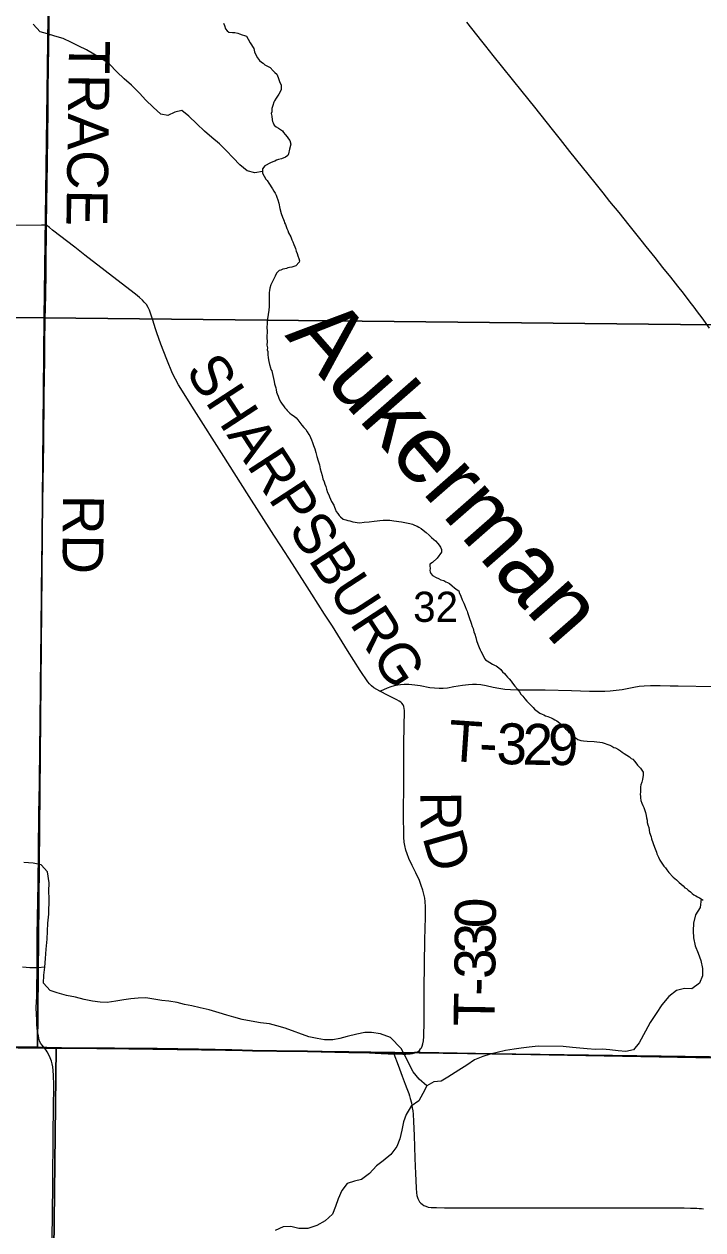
# Model space of a CAD drawing. Extents: x 0 to 34, y 0 to 22.
# Drawn here: x 4.443 to 5.385, y 18.105 to 19.778 of the extents above; entities that cross this region are included whole.
import ezdxf

# ---------------------------------------------------------------- set-up
doc = ezdxf.new("R2010")
doc.units = 0
for name, color, linetype in [('GM_X_Corporation', 7, 'Continuous'), ('GM_X_County_Road', 7, 'Continuous'), ('GM_X_County_Road_Text', 7, 'Continuous'), ('GM_X_Minor_River', 7, 'Continuous'), ('GM_X_Minor_River_Text', 7, 'Continuous'), ('GM_X_Section_Text', 7, 'Continuous'), ('GM_X_State_Route', 7, 'Continuous'), ('GM_X_Township_Road', 7, 'Continuous'), ('GM_X_Township_Road_Text', 7, 'Continuous')]:
    doc.layers.add(name, color=color, linetype=linetype)

msp = doc.modelspace()

# ---------------------------------------------------------------- linework, layer by layer
at = {"layer": 'GM_X_Corporation'}
for points in [[(3.5146, 20.3904), (4.4842, 20.3804), (4.4706, 19.3704), (3.4987, 19.3808), (3.5147, 20.359)], [(4.4842, 20.3804), (5.4958, 20.3705), (5.4859, 19.36), (4.4706, 19.3704)], [(4.4706, 19.3704), (4.4615, 18.3587), (3.4912, 18.3726), (3.4987, 19.3808)], [(5.4859, 19.36), (5.4612, 18.3442), (4.4872, 18.3578), (4.4615, 18.3587), (4.4706, 19.3704)], [(3.4912, 18.3726), (4.4615, 18.3587), (4.4872, 18.3578), (4.475, 17.2762), (3.4847, 17.2912)], [(4.4872, 18.3578), (5.4612, 18.3442), (5.4991, 18.3437), (5.4781, 17.2612), (4.475, 17.2762)]]:
    msp.add_lwpolyline(points, close=True, dxfattribs=at)
for points in [[(6.2163, 18.3289), (4.9929, 18.3512), (4.9848, 18.3513), (4.9816, 18.3505), (4.9785, 18.35), (4.9754, 18.3497), (4.9725, 18.3496), (4.9681, 18.3496), (4.9558, 18.3497), (4.9478, 18.35), (4.9459, 18.3501), (4.9381, 18.3505), (4.9297, 18.3508), (4.9142, 18.3515), (4.8934, 18.3519), (4.8738, 18.3523), (4.8361, 18.353), (4.7933, 18.3536), (4.7598, 18.3542), (4.7312, 18.3548), (4.6851, 18.3558), (4.6275, 18.3567), (4.605, 18.3569), (4.5681, 18.3572), (4.5437, 18.3574), (4.4946, 18.3578), (4.4812, 18.3578), (4.471, 18.3577), (4.4651, 18.3578), (4.3971, 18.3585)], [(4.3971, 18.3585), (4.4651, 18.3578), (4.471, 18.3577), (4.4812, 18.3578), (4.4946, 18.3578), (4.5437, 18.3574), (4.5681, 18.3572), (4.605, 18.3569), (4.6275, 18.3567), (4.6851, 18.3558), (4.7312, 18.3548), (4.7598, 18.3542), (4.7933, 18.3536), (4.8361, 18.353), (4.8738, 18.3523), (4.8934, 18.3519), (4.9142, 18.3515), (4.9297, 18.3508), (4.9381, 18.3505), (4.9459, 18.3501), (4.9478, 18.35), (4.9558, 18.3497), (4.9681, 18.3496), (4.9725, 18.3496), (4.9754, 18.3497), (4.9785, 18.35), (4.9816, 18.3505), (4.9848, 18.3513), (4.9929, 18.3512), (6.2163, 18.3289)]]:
    msp.add_lwpolyline(points, dxfattribs=at)
at = {"layer": 'GM_X_County_Road'}
for points in [[(4.4712, 18.3572), (4.4678, 18.3613), (4.4657, 18.3643), (4.4643, 18.3675), (4.4634, 18.3712), (4.4627, 18.3744), (4.4616, 18.3808), (4.4611, 18.3845), (4.4606, 18.39), (4.4603, 18.3963), (4.46, 18.404), (4.4598, 18.4138), (4.4603, 18.429), (4.4609, 18.4765), (4.4611, 18.514), (4.4622, 18.5858), (4.4629, 18.6294), (4.4635, 18.6835), (4.4641, 18.7233), (4.4647, 18.7767), (4.465, 18.8046), (4.4657, 18.863), (4.4661, 18.8951), (4.4676, 19.0332), (4.4701, 19.1963), (4.4709, 19.2625), (4.4714, 19.3122), (4.4717, 19.3352), (4.4723, 19.3687), (4.4728, 19.4016), (4.4733, 19.4344), (4.4735, 19.4569), (4.4738, 19.4842), (4.474, 19.4994), (4.4744, 19.5295), (4.4753, 19.5861), (4.4758, 19.6233), (4.4761, 19.6582), (4.4764, 19.6872), (4.4772, 19.7476), (4.4779, 19.8035)], [(4.4727, 17.2893), (4.4727, 17.2905), (4.4727, 17.3067), (4.474, 17.3955), (4.4755, 17.5136), (4.4765, 17.5944), (4.4782, 17.7292), (4.4793, 17.8391), (4.4802, 17.9473), (4.4812, 18.0329), (4.482, 18.0907), (4.4827, 18.1677), (4.4833, 18.2397), (4.4839, 18.3062), (4.4838, 18.3193), (4.4834, 18.3262), (4.4827, 18.3312), (4.4817, 18.3355), (4.4807, 18.3391), (4.4789, 18.3438), (4.4765, 18.3487), (4.4749, 18.3519), (4.4733, 18.3544), (4.4712, 18.3572)]]:
    msp.add_lwpolyline(points, dxfattribs=at)
at = {"layer": 'GM_X_Minor_River'}
for points in [[(4.7736, 19.5738), (4.7632, 19.5717), (4.7526, 19.5745), (4.7421, 19.5827), (4.7332, 19.5927), (4.7235, 19.6028), (4.7138, 19.612), (4.7033, 19.6206), (4.6933, 19.6295), (4.6828, 19.6399), (4.6716, 19.6504), (4.6619, 19.6582), (4.652, 19.6557), (4.6424, 19.6513), (4.6326, 19.653), (4.6222, 19.6627), (4.6117, 19.6724), (4.6028, 19.6824), (4.592, 19.6932), (4.5819, 19.7021), (4.5715, 19.7118), (4.5614, 19.7223), (4.5506, 19.7297), (4.5397, 19.7363), (4.5295, 19.7426), (4.519, 19.7477), (4.5085, 19.7525), (4.4972, 19.758), (4.4855, 19.7616), (4.4753, 19.7645), (4.4651, 19.7673), (4.4554, 19.7781)], [(4.7197, 19.7792), (4.7208, 19.7761), (4.7225, 19.7714), (4.7247, 19.7687), (4.7269, 19.7671), (4.7322, 19.7665), (4.7352, 19.7664), (4.7394, 19.7655), (4.742, 19.7646), (4.7457, 19.7634), (4.7487, 19.7625), (4.7513, 19.7613), (4.7538, 19.757), (4.7567, 19.7519), (4.7617, 19.7441), (4.7627, 19.7395), (4.7645, 19.7356), (4.7666, 19.7314), (4.7695, 19.7278), (4.7724, 19.7251), (4.7747, 19.7238), (4.7769, 19.7218), (4.7843, 19.7178), (4.7883, 19.7134), (4.7909, 19.7111), (4.7938, 19.7087), (4.7956, 19.704), (4.7973, 19.6986), (4.7994, 19.6932), (4.7996, 19.6894), (4.7995, 19.6867), (4.7963, 19.6808), (4.7927, 19.6752), (4.7903, 19.6718), (4.7894, 19.6696), (4.7881, 19.6654), (4.7868, 19.6609), (4.7867, 19.6563), (4.7859, 19.6541), (4.7865, 19.6506), (4.7871, 19.6453), (4.7874, 19.643), (4.7884, 19.641), (4.7898, 19.6379), (4.7928, 19.6356), (4.7957, 19.6335), (4.7987, 19.6319), (4.8013, 19.6299), (4.8027, 19.6276), (4.8053, 19.6248), (4.8078, 19.6217), (4.8096, 19.6189), (4.8118, 19.6166), (4.8128, 19.6116), (4.811, 19.6044), (4.8097, 19.598), (4.8088, 19.5957), (4.8057, 19.5936), (4.8003, 19.5911), (4.7957, 19.5901), (4.793, 19.5891), (4.7907, 19.588), (4.788, 19.587), (4.785, 19.5856), (4.7768, 19.5813), (4.7737, 19.5772), (4.7736, 19.5738), (4.7738, 19.5715), (4.7785, 19.5629), (4.7803, 19.561), (4.7825, 19.5575), (4.7875, 19.5497), (4.7893, 19.5465), (4.7911, 19.5434), (4.7925, 19.5407), (4.7935, 19.538), (4.7949, 19.5345), (4.7963, 19.5295), (4.7979, 19.5222), (4.7995, 19.5153), (4.8013, 19.5103), (4.8027, 19.5068), (4.8037, 19.5045), (4.8044, 19.5022), (4.8054, 19.4999), (4.8075, 19.4945), (4.8089, 19.4917), (4.81, 19.4883), (4.8128, 19.4828), (4.8142, 19.479), (4.8156, 19.4759), (4.817, 19.4724), (4.8184, 19.4693)], [(4.8184, 19.4693), (4.8194, 19.4666), (4.8204, 19.4631), (4.8218, 19.4597), (4.8229, 19.4566), (4.8243, 19.4531), (4.8249, 19.4496), (4.8248, 19.4477), (4.8201, 19.4426), (4.8144, 19.4409), (4.8113, 19.4406), (4.809, 19.4399), (4.8071, 19.4392), (4.8048, 19.4386), (4.8017, 19.4379), (4.7991, 19.4369), (4.7968, 19.4362), (4.7932, 19.4325), (4.7912, 19.4284), (4.7855, 19.4164), (4.7838, 19.4119), (4.7833, 19.4085), (4.7828, 19.4055), (4.783, 19.4013), (4.7829, 19.3978), (4.7831, 19.3936), (4.7829, 19.3864), (4.7823, 19.3811), (4.7817, 19.375), (4.7808, 19.369), (4.7802, 19.3644), (4.7801, 19.3614), (4.7796, 19.3587), (4.7799, 19.3557), (4.7802, 19.3534), (4.7801, 19.3496), (4.7799, 19.3461), (4.7798, 19.3427), (4.78, 19.3378), (4.7799, 19.3328), (4.7805, 19.329), (4.7804, 19.3263), (4.7811, 19.324), (4.7813, 19.3198), (4.7815, 19.3152), (4.7825, 19.3102), (4.7835, 19.3056), (4.7848, 19.3014), (4.7855, 19.2991), (4.7866, 19.2968), (4.7872, 19.2945), (4.7898, 19.2822), (4.7905, 19.2791), (4.7915, 19.2764), (4.7922, 19.2733), (4.7925, 19.2707), (4.7931, 19.2676), (4.7942, 19.2653), (4.7956, 19.2618), (4.7969, 19.2575), (4.7991, 19.2537), (4.8009, 19.2509), (4.8027, 19.2486), (4.8048, 19.2458), (4.8067, 19.2439), (4.8081, 19.2419), (4.8096, 19.24), (4.8118, 19.2383), (4.814, 19.2364), (4.8177, 19.2339), (4.8203, 19.2319), (4.8228, 19.2288), (4.8254, 19.2253), (4.8283, 19.2218), (4.8312, 19.2186), (4.8337, 19.2155), (4.8359, 19.2123), (4.838, 19.2088), (4.8395, 19.2069), (4.8405, 19.2046), (4.8419, 19.2011), (4.8433, 19.1976), (4.8447, 19.1934), (4.8464, 19.1887), (4.8478, 19.1837), (4.8491, 19.178), (4.8508, 19.1722), (4.8528, 19.1664), (4.8538, 19.161), (4.8565, 19.1518), (4.8575, 19.1472), (4.8592, 19.1429), (4.8603, 19.1399), (4.8616, 19.1364), (4.8627, 19.1329), (4.864, 19.1283), (4.8658, 19.1248), (4.8668, 19.1221), (4.8696, 19.1159), (4.8725, 19.1105), (4.8735, 19.1078)], [(4.8735, 19.1078), (4.8746, 19.1055), (4.876, 19.102), (4.8781, 19.0989), (4.88, 19.0965), (4.8818, 19.0945), (4.8858, 19.0913), (4.8892, 19.0901), (4.8922, 19.0892), (4.8948, 19.0887), (4.8993, 19.0874), (4.9024, 19.0869), (4.905, 19.0868), (4.9088, 19.0863), (4.9149, 19.0869), (4.9217, 19.0874), (4.9286, 19.0886), (4.9328, 19.0889), (4.9366, 19.0895), (4.9411, 19.0897), (4.9461, 19.0899), (4.9502, 19.0898), (4.9562, 19.0888), (4.9596, 19.0883), (4.9627, 19.0878), (4.9664, 19.0873), (4.9781, 19.085), (4.9819, 19.0841), (4.9848, 19.0828), (4.9882, 19.0815), (4.9908, 19.0803), (4.9938, 19.0783), (4.9967, 19.0759), (5.0008, 19.0727), (5.0048, 19.0691), (5.0081, 19.0656), (5.0114, 19.0628), (5.014, 19.0612), (5.0169, 19.0573), (5.0187, 19.0553), (5.0209, 19.0522), (5.0223, 19.0491), (5.0222, 19.0453), (5.0162, 19.0371), (5.0096, 19.0309), (5.0061, 19.0287), (5.006, 19.0264), (5.0062, 19.0226), (5.0061, 19.02), (5.0064, 19.018), (5.0075, 19.0157), (5.0097, 19.013), (5.0149, 19.0101), (5.0179, 19.0089), (5.0212, 19.0072), (5.0254, 19.0059), (5.0283, 19.0043), (5.0306, 19.0035), (5.0332, 19.0018), (5.0368, 18.9987), (5.0402, 18.9959), (5.0439, 18.9931), (5.0461, 18.9919), (5.0468, 18.9896), (5.0489, 18.9845), (5.0509, 18.9791), (5.0531, 18.9745), (5.0548, 18.9702), (5.0562, 18.9664), (5.0576, 18.9636), (5.0583, 18.9617), (5.0597, 18.9575), (5.0607, 18.9548), (5.0631, 18.9467), (5.0648, 18.9424), (5.0662, 18.9393), (5.0665, 18.9374), (5.0672, 18.9351), (5.0682, 18.9317), (5.0696, 18.927), (5.0709, 18.9228), (5.0727, 18.9178), (5.0744, 18.9132), (5.0758, 18.9101), (5.0769, 18.9081), (5.0786, 18.9046), (5.0818, 18.898), (5.0833, 18.8961), (5.0855, 18.8945), (5.0892, 18.8924), (5.0929, 18.89), (5.0959, 18.8888), (5.0981, 18.8875), (5.1018, 18.8847), (5.1044, 18.8824), (5.107, 18.8796), (5.1095, 18.8772), (5.1113, 18.8749), (5.1135, 18.8721), (5.1161, 18.8698), (5.1186, 18.8666)], [(5.1186, 18.8666), (5.1208, 18.8635), (5.1237, 18.8596), (5.1277, 18.8553), (5.1302, 18.8517), (5.1324, 18.8486), (5.1349, 18.8455), (5.1378, 18.8419), (5.1404, 18.8388), (5.143, 18.8364), (5.1448, 18.8345), (5.1477, 18.8317), (5.1492, 18.8297), (5.151, 18.8278), (5.1532, 18.8261), (5.1584, 18.8222), (5.1617, 18.8205), (5.164, 18.8197), (5.1666, 18.8184), (5.1696, 18.8172), (5.1718, 18.8163), (5.1741, 18.8155), (5.1771, 18.8142), (5.1796, 18.8126), (5.1823, 18.8114), (5.1863, 18.8082), (5.1944, 18.8003), (5.1966, 18.7983), (5.1984, 18.7963), (5.2017, 18.7932), (5.2061, 18.7892), (5.2091, 18.7872), (5.2113, 18.7856), (5.2154, 18.7843), (5.2192, 18.7838), (5.2241, 18.7832), (5.2339, 18.7829), (5.2377, 18.7823), (5.2419, 18.7818), (5.2449, 18.7813), (5.2494, 18.78), (5.2516, 18.7792), (5.2557, 18.7775), (5.2587, 18.7763), (5.2613, 18.7746), (5.2636, 18.7738), (5.2676, 18.7714), (5.2706, 18.7697), (5.2728, 18.7681), (5.2758, 18.7661), (5.2791, 18.7637), (5.2828, 18.7613), (5.2854, 18.7593), (5.2876, 18.7581), (5.2902, 18.7553), (5.2916, 18.753), (5.2942, 18.7498), (5.2982, 18.7455), (5.3018, 18.74), (5.302, 18.7358), (5.3011, 18.7302), (5.3002, 18.7264), (5.2989, 18.7226), (5.2984, 18.7196), (5.2982, 18.7128), (5.2977, 18.709), (5.2984, 18.707), (5.2983, 18.7044), (5.2989, 18.7009), (5.3003, 18.6971), (5.3017, 18.694), (5.3027, 18.6913), (5.3038, 18.6882), (5.3051, 18.6843), (5.3061, 18.6801), (5.3068, 18.6767), (5.3074, 18.6736), (5.3077, 18.6705), (5.3087, 18.6671), (5.3097, 18.6632), (5.311, 18.6563), (5.3131, 18.6505), (5.3137, 18.6475), (5.3178, 18.6359), (5.3185, 18.6336), (5.3196, 18.6313), (5.3203, 18.6293), (5.3209, 18.627), (5.322, 18.6251), (5.3231, 18.6224), (5.3252, 18.6181), (5.3277, 18.6138), (5.3306, 18.6099), (5.3331, 18.6072), (5.3349, 18.6048), (5.3378, 18.6009), (5.3437, 18.5946), (5.3459, 18.5926), (5.3481, 18.591), (5.3499, 18.589), (5.3521, 18.5871)], [(5.0016, 18.3048), (4.9912, 18.3141), (4.983, 18.3245), (4.9779, 18.3341), (4.9724, 18.3448), (4.9662, 18.3567), (4.9513, 18.3721), (4.9373, 18.3773), (4.9252, 18.3791), (4.9157, 18.3789), (4.9047, 18.3768), (4.8913, 18.3733), (4.881, 18.3708), (4.8711, 18.3687), (4.8598, 18.3689), (4.8495, 18.3706), (4.8378, 18.3731), (4.805, 18.3851), (4.7937, 18.3883), (4.7835, 18.3908), (4.771, 18.3925), (4.7578, 18.3947), (4.7457, 18.3972), (4.734, 18.4004), (4.7242, 18.4029), (4.7136, 18.4061), (4.6996, 18.4102), (4.6872, 18.4131), (4.6755, 18.4159), (4.6656, 18.418), (4.6554, 18.4205), (4.6437, 18.4222), (4.6339, 18.4235), (4.6119, 18.427), (4.6013, 18.4268), (4.591, 18.4258), (4.5811, 18.4245), (4.5701, 18.4224), (4.5583, 18.4208), (4.5484, 18.4209), (4.5378, 18.4223), (4.5261, 18.4248), (4.514, 18.428), (4.5016, 18.4305), (4.4887, 18.4338), (4.4789, 18.437), (4.4696, 18.4474), (4.4702, 18.4584), (4.4715, 18.4694), (4.4725, 18.4815), (4.4735, 18.4948), (4.4749, 18.5084), (4.4755, 18.5197), (4.4757, 18.5307), (4.4771, 18.5432), (4.4775, 18.5648), (4.4773, 18.5751), (4.4775, 18.5868), (4.4755, 18.6017), (4.4666, 18.6117), (4.4556, 18.6138), (4.4423, 18.6148)], [(5.3521, 18.5871), (5.3547, 18.5847), (5.3577, 18.5823), (5.3598, 18.5799), (5.3621, 18.5787), (5.3646, 18.5763), (5.3676, 18.5739), (5.3698, 18.572), (5.3724, 18.57), (5.375, 18.5687), (5.3776, 18.5671), (5.3802, 18.5659), (5.3824, 18.5646), (5.3854, 18.5626)], [(5.3824, 18.5646), (5.3811, 18.5522), (5.3744, 18.5421), (5.3719, 18.5308), (5.3714, 18.5202), (5.372, 18.5103), (5.374, 18.4993), (5.3784, 18.489), (5.382, 18.479), (5.3844, 18.4676), (5.3843, 18.4578), (5.3803, 18.4476), (5.3695, 18.4394), (5.3593, 18.44), (5.3482, 18.4372), (5.3374, 18.4287), (5.3277, 18.4175), (5.3199, 18.4055), (5.3117, 18.3927), (5.3054, 18.3807), (5.2964, 18.3646), (5.2887, 18.3549), (5.278, 18.3524), (5.2674, 18.3537), (5.2556, 18.3547), (5.2454, 18.3557), (5.2359, 18.3555), (5.2242, 18.3564), (5.2143, 18.3574), (5.2041, 18.3583), (5.1912, 18.3593), (5.1563, 18.36), (5.1438, 18.3587), (5.1327, 18.3574), (5.1232, 18.3557), (5.1111, 18.354), (5.0996, 18.3512), (5.0897, 18.3487), (5.0794, 18.3455), (5.0679, 18.3408), (5.0572, 18.3338), (5.0461, 18.3268), (5.0311, 18.3172), (5.0215, 18.3113), (5.0116, 18.3103), (5.0016, 18.3048), (4.9961, 18.2943), (4.9906, 18.2842), (4.9802, 18.2768), (4.9732, 18.2652), (4.9696, 18.255), (4.9671, 18.2433), (4.9642, 18.2316), (4.9602, 18.221), (4.9517, 18.2098), (4.9413, 18.2009), (4.9317, 18.1939), (4.922, 18.1831), (4.9112, 18.1749), (4.9013, 18.1728), (4.891, 18.1692), (4.8836, 18.1595), (4.8788, 18.1482), (4.8752, 18.1373), (4.8709, 18.1268), (4.8608, 18.1178), (4.8489, 18.1112), (4.8367, 18.1069), (4.8242, 18.1071), (4.8129, 18.1096), (4.8026, 18.1094), (4.7915, 18.1043)], [(4.4715, 18.4694), (4.4617, 18.4688), (4.451, 18.4686), (4.4408, 18.4696)]]:
    msp.add_lwpolyline(points, dxfattribs=at)
at = {"layer": 'GM_X_State_Route'}
msp.add_lwpolyline([(5.0567, 19.7806), (5.0776, 19.7544), (5.083, 19.7476), (5.0935, 19.7345), (5.1335, 19.6845), (5.151, 19.6627), (5.1759, 19.6317), (5.1868, 19.6179), (5.1999, 19.6015), (5.2347, 19.5578), (5.246, 19.5438), (5.2554, 19.5322), (5.268, 19.5168), (5.2819, 19.4993), (5.2912, 19.4876), (5.2986, 19.4783), (5.3055, 19.4696), (5.318, 19.4541), (5.3289, 19.4406), (5.3398, 19.427), (5.3498, 19.4143), (5.3575, 19.4046), (5.3669, 19.3923), (5.3722, 19.3855), (5.377, 19.3789), (5.3833, 19.3704), (5.3936, 19.3561)], dxfattribs=at)
at = {"layer": 'GM_X_Township_Road'}
for points in [[(4.4299, 19.4993), (4.467, 19.4994), (4.4698, 19.4994), (4.474, 19.4994)], [(4.9365, 18.8526), (4.9323, 18.8548), (4.9283, 18.8574), (4.9249, 18.8601), (4.9222, 18.8628), (4.92, 18.8656), (4.9094, 18.8812), (4.8918, 18.909), (4.8707, 18.9427), (4.8599, 18.9594), (4.8422, 18.9871), (4.8154, 19.029), (4.7993, 19.0541), (4.7895, 19.0692), (4.752, 19.1278), (4.7201, 19.1782), (4.6788, 19.2431), (4.6572, 19.2776), (4.6489, 19.2935), (4.6409, 19.3126), (4.6367, 19.3234), (4.6328, 19.334), (4.627, 19.3499), (4.6252, 19.3554), (4.6216, 19.3674), (4.6185, 19.3772), (4.6169, 19.3814), (4.6151, 19.3851), (4.6126, 19.3889), (4.6097, 19.3925), (4.607, 19.3951), (4.6032, 19.3987), (4.5975, 19.4035), (4.5836, 19.4142), (4.5271, 19.4577), (4.5132, 19.4684), (4.4824, 19.4922), (4.478, 19.4957), (4.4762, 19.4972), (4.474, 19.4994)], [(4.9365, 18.8526), (4.9422, 18.855), (4.9473, 18.8572), (4.9522, 18.8592), (4.9569, 18.8605), (4.9614, 18.8615), (4.9654, 18.862), (4.9701, 18.8623), (4.977, 18.8621), (4.985, 18.8613), (4.9924, 18.8603), (5.0058, 18.8578), (5.0126, 18.857), (5.0188, 18.8567), (5.0244, 18.8568), (5.0306, 18.8574), (5.0392, 18.8588), (5.0514, 18.861), (5.0594, 18.862), (5.065, 18.8623), (5.0706, 18.8622), (5.0767, 18.8616), (5.084, 18.8603), (5.0937, 18.8581), (5.1016, 18.8566), (5.1102, 18.8553), (5.1177, 18.8547), (5.1276, 18.8544), (5.1363, 18.8544), (5.1456, 18.8545), (5.1661, 18.8545), (5.2027, 18.8534), (5.2276, 18.8527), (5.2369, 18.8525), (5.2487, 18.8525), (5.2561, 18.8528), (5.2647, 18.8538), (5.2727, 18.855), (5.2892, 18.8583), (5.2965, 18.8594), (5.3036, 18.8599), (5.3121, 18.8603), (5.3257, 18.8603), (5.3394, 18.8601), (5.3505, 18.8598), (5.4001, 18.859)], [(4.9932, 18.3561), (4.9943, 18.3576), (4.9953, 18.3602), (4.9963, 18.3631), (4.9971, 18.3673), (4.9976, 18.3734), (4.998, 18.3942), (4.9982, 18.4395), (4.9991, 18.5077), (4.9997, 18.5388), (4.9998, 18.5531), (4.9994, 18.5605), (4.9988, 18.5654), (4.9978, 18.5709), (4.9964, 18.5763), (4.9941, 18.5828), (4.9914, 18.5897), (4.9865, 18.6004), (4.9816, 18.6105), (4.9769, 18.6206), (4.9743, 18.6268), (4.9726, 18.6319), (4.9711, 18.6382), (4.9704, 18.6432), (4.9698, 18.65), (4.9696, 18.6835), (4.9699, 18.7239), (4.9699, 18.7804), (4.9706, 18.8256), (4.9703, 18.8287), (4.9698, 18.8312), (4.9687, 18.8337), (4.9673, 18.8357), (4.9658, 18.8373), (4.9636, 18.8388), (4.9602, 18.8406), (4.9482, 18.8464), (4.9365, 18.8526)], [(3.4872, 18.3713), (3.4878, 18.3713), (3.5208, 18.3712), (3.5736, 18.3709), (3.5929, 18.3709), (3.6165, 18.3706), (3.645, 18.3704), (3.7389, 18.3688), (3.782, 18.3683), (3.8153, 18.3679), (3.8494, 18.3674), (3.9035, 18.3665), (3.9929, 18.3658), (4.07, 18.3646), (4.1228, 18.3634), (4.1706, 18.3621), (4.3532, 18.3587), (4.3974, 18.358), (4.4712, 18.3572)], [(4.4712, 18.3572), (4.4814, 18.3573), (4.4948, 18.3572), (4.5439, 18.3569), (4.5683, 18.3567), (4.6052, 18.3564), (4.6278, 18.3561), (4.6854, 18.3553), (4.7315, 18.3543), (4.76, 18.3536), (4.7935, 18.3531), (4.8363, 18.3525), (4.874, 18.3518), (4.8936, 18.3514), (4.9144, 18.351), (4.9299, 18.3503), (4.9383, 18.3499), (4.9461, 18.3496), (4.9481, 18.3495), (4.956, 18.3492)], [(4.956, 18.3492), (4.9684, 18.3491), (4.9727, 18.349), (4.9756, 18.3492), (4.9787, 18.3494), (4.9819, 18.35), (4.985, 18.3508), (4.9875, 18.3516), (4.9896, 18.3528), (4.9914, 18.354), (4.9932, 18.3561)], [(4.956, 18.3492), (4.9619, 18.3334), (4.9677, 18.3183), (4.9719, 18.3073), (4.9742, 18.3012), (4.9766, 18.2944), (4.9777, 18.2909), (4.9788, 18.2873), (4.9803, 18.2812), (4.981, 18.2777), (4.9816, 18.2744), (4.9822, 18.2704), (4.9828, 18.2655), (4.9833, 18.2554), (4.9837, 18.2456), (4.9841, 18.2359), (4.9851, 18.2046), (4.9855, 18.1934), (4.9859, 18.1835), (4.9863, 18.1737), (4.9868, 18.1629), (4.9873, 18.1564), (4.988, 18.1526), (4.9893, 18.1485), (4.9905, 18.1458), (4.9918, 18.1439), (4.9933, 18.1421), (4.9951, 18.1406), (4.9976, 18.139), (5.0003, 18.1378), (5.0037, 18.1368), (5.0078, 18.1362), (5.0114, 18.1359), (5.0152, 18.1359), (5.0264, 18.1358), (5.0381, 18.1358), (5.0644, 18.1357), (5.0894, 18.1357), (5.1305, 18.1358), (5.144, 18.1358), (5.1918, 18.1357), (5.2633, 18.1355), (5.3229, 18.1355), (5.3509, 18.1355), (5.359, 18.1355), (5.3676, 18.1354), (5.3764, 18.1351), (5.3797, 18.1349), (5.3829, 18.1346), (5.3856, 18.1341)]]:
    msp.add_lwpolyline(points, dxfattribs=at)

# ---------------------------------------------------------------- texts
at = {"layer": 'GM_X_County_Road_Text'}
for s, rotation, p in [('TRACE', 269.1606, (4.5053, 19.7557)), ('RD', 269.5054, (4.4968, 19.1251))]:
    msp.add_text(s, height=0.05682, rotation=rotation, dxfattribs=at).set_placement(p)
at = {"layer": 'GM_X_Minor_River_Text'}
msp.add_text('Aukerman', height=0.09471, rotation=311.2106, dxfattribs=at).set_placement((4.8038, 19.3457))
at = {"layer": 'GM_X_Section_Text'}
msp.add_text('32', height=0.04186, rotation=0, dxfattribs=at).set_placement((4.9828, 18.9487))
at = {"layer": 'GM_X_Township_Road_Text'}
for s, height, rotation, p in [('SHARPSBURG', 0.05682, 303.0809, (4.6657, 19.2967)), ('T', 0.0568, 356.0928, (5.0301, 18.7561)), ('3', 0.0568, 358.0339, (5.0979, 18.7518)), ('2', 0.0568, 359.1911, (5.1342, 18.7506)), ('9', 0.0568, 359.9167, (5.1699, 18.7501)), ('-', 0.0568, 356.8394, (5.0733, 18.7532)), ('R', 0.0568, 270.4762, (4.9927, 18.7132)), ('D', 0.0568, 285.9045, (4.9954, 18.6503)), ('0', 0.0568, 89.7521, (5.0975, 18.5237)), ('3', 0.0568, 89.3405, (5.0971, 18.4882)), ('3', 0.0568, 89.1812, (5.0966, 18.4531)), ('-', 0.0568, 89.1413, (5.0962, 18.4297)), ('T', 0.0568, 89.1278, (5.0956, 18.3872))]:
    msp.add_text(s, height=height, rotation=rotation, dxfattribs=at).set_placement(p)

doc.saveas('drawing.dxf')
